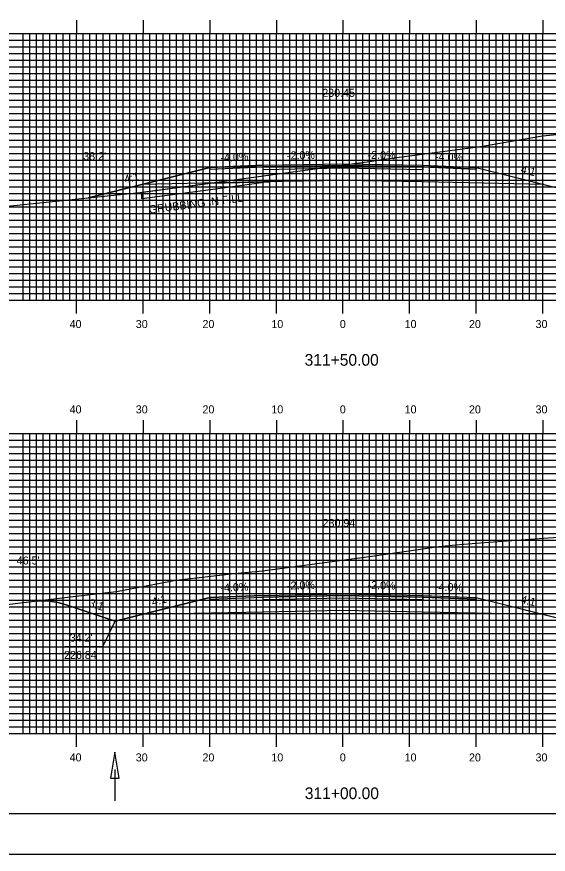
# Model space of a CAD drawing. Extents: x 1818457 to 1818800, y 442591 to 442811.
# Drawn here: x 1818573.7 to 1818653.4, y 442590.5 to 442716.2 of the extents above; entities that cross this region are included whole.
import ezdxf

# ---------------------------------------------------------------- set-up
doc = ezdxf.new("R2010")
doc.units = 0
for name, color, linetype in [('ANNOTATION', 7, 'Continuous'), ('BORDER', 7, 'Continuous'), ('D_Drainage_Ditch_Line', 7, 'Continuous'), ('D_Roadway_Centerline', 7, 'Continuous'), ('D_Roadway_Centerline_Text', 7, 'Continuous'), ('D_Roadway_Edge_Shoulder', 7, 'Continuous'), ('D_Roadway_Edge_TW', 7, 'Continuous'), ('D_Roadway_Pavement', 7, 'Continuous'), ('D_Roadway_SlopeLines', 7, 'Continuous'), ('D_Roadway_SubGrade', 7, 'Continuous'), ('D_Text_Standard', 7, 'Continuous'), ('GRUBBING IN FILL', 7, 'Continuous'), ('H_V ANNOTATION', 7, 'Continuous'), ('MAJOR', 7, 'Continuous'), ('MINOR', 7, 'Continuous'), ('PLOT BOUNDARY', 7, 'Continuous'), ('S_Roadway_Centerline', 7, 'Continuous')]:
    doc.layers.add(name, color=color, linetype=linetype)

msp = doc.modelspace()

# ---------------------------------------------------------------- linework, layer by layer
at = {"layer": 'ANNOTATION'}
msp.add_lwpolyline([(1818580.89, 442621.71), (1818586.58, 442621.71), (1818588.46, 442625.5)], dxfattribs=at)
at = {"layer": 'BORDER'}
msp.add_lwpolyline([(1818473.04, 442596.67), (1818793.04, 442596.67), (1818793.04, 442806.67), (1818473.04, 442806.67)], close=True, dxfattribs=at)
at = {"layer": 'D_Drainage_Ditch_Line'}
msp.add_line((1818588.38, 442603.26), (1818588.38, 442598.56), dxfattribs=at)
msp.add_lwpolyline([(1818587.72, 442601.95), (1818589.03, 442601.95), (1818588.38, 442605.88)], close=True, dxfattribs=at)
at = {"layer": 'D_Roadway_Centerline'}
for points in [[(1818584.45, 442689.01), (1818590.64, 442690.56), (1818592.46, 442691.02), (1818602.64, 442693.56), (1818610.64, 442693.88), (1818622.64, 442694.12), (1818634.64, 442693.88), (1818642.64, 442693.56), (1818652.81, 442691.02), (1818656.81, 442690.02), (1818690.05, 442701.1), (1818691.3, 442701.47), (1818692.55, 442701.76), (1818693.8, 442701.97), (1818695.05, 442702.1)], [(1818576.1, 442628.49), (1818577.35, 442628.57), (1818578.6, 442628.51), (1818579.85, 442628.3), (1818581.1, 442627.96), (1818588.46, 442625.5), (1818592.46, 442626.5), (1818602.64, 442629.05), (1818610.64, 442629.37), (1818622.64, 442629.61), (1818634.64, 442629.37), (1818642.64, 442629.05), (1818652.81, 442626.5), (1818656.81, 442625.5), (1818703.88, 442641.19), (1818705.13, 442641.57), (1818706.38, 442641.86), (1818707.63, 442642.06), (1818708.88, 442642.19)]]:
    msp.add_lwpolyline(points, dxfattribs=at)
at = {"layer": 'D_Roadway_Edge_Shoulder'}
for points in [[(1818610.64, 442693.88), (1818602.64, 442693.56), (1818602.64, 442693.31), (1818610.64, 442693.63)], [(1818634.64, 442693.88), (1818642.64, 442693.56), (1818642.64, 442693.31), (1818634.64, 442693.63)], [(1818610.64, 442629.37), (1818602.64, 442629.05), (1818602.64, 442628.8), (1818610.64, 442629.12)], [(1818634.64, 442629.37), (1818642.64, 442629.05), (1818642.64, 442628.8), (1818634.64, 442629.12)]]:
    msp.add_lwpolyline(points, close=True, dxfattribs=at)
at = {"layer": 'D_Roadway_Edge_TW'}
for points in [[(1818610.64, 442693.63), (1818610.64, 442693.88), (1818622.64, 442694.12), (1818634.64, 442693.88), (1818634.64, 442693.63), (1818622.64, 442693.87)], [(1818610.64, 442629.12), (1818610.64, 442629.37), (1818622.64, 442629.61), (1818634.64, 442629.37), (1818634.64, 442629.12), (1818622.64, 442629.36)]]:
    msp.add_lwpolyline(points, close=True, dxfattribs=at)
at = {"layer": 'D_Roadway_Pavement'}
for points in [[(1818610.64, 442693.21), (1818610.64, 442693.63), (1818622.64, 442693.87), (1818634.64, 442693.63), (1818634.64, 442693.21), (1818622.64, 442693.45)], [(1818610.64, 442628.7), (1818610.64, 442629.12), (1818622.64, 442629.36), (1818634.64, 442629.12), (1818634.64, 442628.7), (1818622.64, 442628.94)]]:
    msp.add_lwpolyline(points, close=True, dxfattribs=at)
at = {"layer": 'D_Roadway_SlopeLines'}
for points in [[(1818602.64, 442693.56), (1818592.46, 442691.02), (1818590.64, 442690.56), (1818584.45, 442689.01)], [(1818642.64, 442693.56), (1818656.81, 442690.02)], [(1818588.46, 442625.5), (1818581.1, 442627.96), (1818579.85, 442628.3), (1818578.6, 442628.51), (1818577.35, 442628.57), (1818576.1, 442628.49)], [(1818602.64, 442629.05), (1818588.46, 442625.5)], [(1818642.64, 442629.05), (1818656.81, 442625.5)]]:
    msp.add_lwpolyline(points, dxfattribs=at)
at = {"layer": 'D_Roadway_SubGrade'}
for points in [[(1818610.64, 442691.38), (1818592.46, 442691.02), (1818602.64, 442693.56), (1818602.64, 442693.31), (1818610.64, 442693.63), (1818622.64, 442693.87), (1818634.64, 442693.63), (1818642.64, 442693.31), (1818642.64, 442693.56), (1818652.81, 442691.02), (1818634.64, 442691.38), (1818622.64, 442691.62)], [(1818610.64, 442626.87), (1818592.46, 442626.5), (1818602.64, 442629.05), (1818602.64, 442628.8), (1818610.64, 442629.12), (1818622.64, 442629.36), (1818634.64, 442629.12), (1818642.64, 442628.8), (1818642.64, 442629.05), (1818652.81, 442626.5), (1818634.64, 442626.87), (1818622.64, 442627.11)]]:
    msp.add_lwpolyline(points, close=True, dxfattribs=at)
at = {"layer": 'GRUBBING IN FILL'}
msp.add_lwpolyline([(1818592.46, 442689.84), (1818602.73, 442691.22), (1818611.52, 442691.4), (1818602.73, 442690.21), (1818592.46, 442688.83)], close=True, dxfattribs=at)
msp.add_lwpolyline([(1818592.46, 442689.84), (1818602.73, 442691.22), (1818611.52, 442691.4), (1818602.73, 442690.21), (1818592.46, 442688.83)], close=True, dxfattribs=at)
at = {"layer": 'MAJOR'}
for p, q in [((1818582.64, 442715.67), (1818582.64, 442713.67)), ((1818592.64, 442715.67), (1818592.64, 442713.67)), ((1818602.64, 442715.67), (1818602.64, 442713.67)), ((1818612.64, 442715.67), (1818612.64, 442713.67)), ((1818622.64, 442715.67), (1818622.64, 442713.67)), ((1818632.64, 442715.67), (1818632.64, 442713.67)), ((1818642.64, 442715.67), (1818642.64, 442713.67)), ((1818652.64, 442715.67), (1818652.64, 442713.67)), ((1818482.64, 442713.67), (1818762.64, 442713.67)), ((1818482.64, 442713.67), (1818762.64, 442713.67)), ((1818582.64, 442673.67), (1818582.64, 442713.67)), ((1818592.64, 442673.67), (1818592.64, 442713.67)), ((1818602.64, 442673.67), (1818602.64, 442713.67)), ((1818612.64, 442673.67), (1818612.64, 442713.67)), ((1818622.64, 442673.67), (1818622.64, 442713.67)), ((1818632.64, 442673.67), (1818632.64, 442713.67)), ((1818642.64, 442673.67), (1818642.64, 442713.67)), ((1818652.64, 442673.67), (1818652.64, 442713.67)), ((1818482.64, 442708.67), (1818762.64, 442708.67)), ((1818482.64, 442703.67), (1818762.64, 442703.67)), ((1818482.64, 442698.67), (1818762.64, 442698.67)), ((1818482.64, 442693.67), (1818762.64, 442693.67)), ((1818482.64, 442688.67), (1818762.64, 442688.67)), ((1818482.64, 442683.67), (1818762.64, 442683.67)), ((1818482.64, 442678.67), (1818762.64, 442678.67)), ((1818482.64, 442673.67), (1818762.64, 442673.67)), ((1818482.64, 442673.67), (1818762.64, 442673.67)), ((1818582.64, 442671.66), (1818582.64, 442673.67)), ((1818592.64, 442671.66), (1818592.64, 442673.67)), ((1818602.64, 442671.66), (1818602.64, 442673.67)), ((1818612.64, 442671.66), (1818612.64, 442673.67)), ((1818622.64, 442671.66), (1818622.64, 442673.67)), ((1818632.64, 442671.66), (1818632.64, 442673.67)), ((1818642.64, 442671.66), (1818642.64, 442673.67)), ((1818652.64, 442671.66), (1818652.64, 442673.67)), ((1818582.64, 442655.67), (1818582.64, 442653.67)), ((1818592.64, 442655.67), (1818592.64, 442653.67)), ((1818602.64, 442655.67), (1818602.64, 442653.67)), ((1818612.64, 442655.67), (1818612.64, 442653.67)), ((1818622.64, 442655.67), (1818622.64, 442653.67)), ((1818632.64, 442655.67), (1818632.64, 442653.67)), ((1818642.64, 442655.67), (1818642.64, 442653.67)), ((1818652.64, 442655.67), (1818652.64, 442653.67)), ((1818482.64, 442653.67), (1818762.64, 442653.67)), ((1818482.64, 442653.67), (1818762.64, 442653.67)), ((1818582.64, 442608.67), (1818582.64, 442653.67)), ((1818592.64, 442608.67), (1818592.64, 442653.67)), ((1818602.64, 442608.67), (1818602.64, 442653.67)), ((1818612.64, 442608.67), (1818612.64, 442653.67)), ((1818622.64, 442608.67), (1818622.64, 442653.67)), ((1818632.64, 442608.67), (1818632.64, 442653.67)), ((1818642.64, 442608.67), (1818642.64, 442653.67)), ((1818652.64, 442608.67), (1818652.64, 442653.67)), ((1818482.64, 442648.67), (1818762.64, 442648.67)), ((1818482.64, 442643.67), (1818762.64, 442643.67)), ((1818482.64, 442638.67), (1818762.64, 442638.67)), ((1818482.64, 442633.67), (1818762.64, 442633.67)), ((1818482.64, 442628.67), (1818762.64, 442628.67)), ((1818482.64, 442623.67), (1818762.64, 442623.67)), ((1818482.64, 442618.67), (1818762.64, 442618.67)), ((1818482.64, 442613.67), (1818762.64, 442613.67)), ((1818482.64, 442608.67), (1818762.64, 442608.67)), ((1818482.64, 442608.67), (1818762.64, 442608.67)), ((1818582.64, 442606.66), (1818582.64, 442608.67)), ((1818592.64, 442606.66), (1818592.64, 442608.67)), ((1818602.64, 442606.66), (1818602.64, 442608.67)), ((1818612.64, 442606.66), (1818612.64, 442608.67)), ((1818622.64, 442606.66), (1818622.64, 442608.67)), ((1818632.64, 442606.66), (1818632.64, 442608.67)), ((1818642.64, 442606.66), (1818642.64, 442608.67)), ((1818652.64, 442606.66), (1818652.64, 442608.67))]:
    msp.add_line(p, q, dxfattribs=at)
at = {"layer": 'MINOR'}
for p, q in [((1818574.64, 442673.67), (1818574.64, 442713.67)), ((1818575.64, 442673.67), (1818575.64, 442713.67)), ((1818576.64, 442673.67), (1818576.64, 442713.67)), ((1818577.64, 442673.67), (1818577.64, 442713.67)), ((1818578.64, 442673.67), (1818578.64, 442713.67)), ((1818579.64, 442673.67), (1818579.64, 442713.67)), ((1818580.64, 442673.67), (1818580.64, 442713.67)), ((1818581.64, 442673.67), (1818581.64, 442713.67)), ((1818583.64, 442673.67), (1818583.64, 442713.67)), ((1818584.64, 442673.67), (1818584.64, 442713.67)), ((1818585.64, 442673.67), (1818585.64, 442713.67)), ((1818586.64, 442673.67), (1818586.64, 442713.67)), ((1818587.64, 442673.67), (1818587.64, 442713.67)), ((1818588.64, 442673.67), (1818588.64, 442713.67)), ((1818589.64, 442673.67), (1818589.64, 442713.67)), ((1818590.64, 442673.67), (1818590.64, 442713.67)), ((1818591.64, 442673.67), (1818591.64, 442713.67)), ((1818593.64, 442673.67), (1818593.64, 442713.67)), ((1818594.64, 442673.67), (1818594.64, 442713.67)), ((1818595.64, 442673.67), (1818595.64, 442713.67)), ((1818596.64, 442673.67), (1818596.64, 442713.67)), ((1818597.64, 442673.67), (1818597.64, 442713.67)), ((1818598.64, 442673.67), (1818598.64, 442713.67)), ((1818599.64, 442673.67), (1818599.64, 442713.67)), ((1818600.64, 442673.67), (1818600.64, 442713.67)), ((1818601.64, 442673.67), (1818601.64, 442713.67)), ((1818603.64, 442673.67), (1818603.64, 442713.67)), ((1818604.64, 442673.67), (1818604.64, 442713.67)), ((1818605.64, 442673.67), (1818605.64, 442713.67)), ((1818606.64, 442673.67), (1818606.64, 442713.67)), ((1818607.64, 442673.67), (1818607.64, 442713.67)), ((1818608.64, 442673.67), (1818608.64, 442713.67)), ((1818609.64, 442673.67), (1818609.64, 442713.67)), ((1818610.64, 442673.67), (1818610.64, 442713.67)), ((1818611.64, 442673.67), (1818611.64, 442713.67)), ((1818613.64, 442673.67), (1818613.64, 442713.67)), ((1818614.64, 442673.67), (1818614.64, 442713.67)), ((1818615.64, 442673.67), (1818615.64, 442713.67)), ((1818616.64, 442673.67), (1818616.64, 442713.67)), ((1818617.64, 442673.67), (1818617.64, 442713.67)), ((1818618.64, 442673.67), (1818618.64, 442713.67)), ((1818619.64, 442673.67), (1818619.64, 442713.67)), ((1818620.64, 442673.67), (1818620.64, 442713.67)), ((1818621.64, 442673.67), (1818621.64, 442713.67)), ((1818623.64, 442673.67), (1818623.64, 442713.67)), ((1818624.64, 442673.67), (1818624.64, 442713.67)), ((1818625.64, 442673.67), (1818625.64, 442713.67)), ((1818626.64, 442673.67), (1818626.64, 442713.67)), ((1818627.64, 442673.67), (1818627.64, 442713.67)), ((1818628.64, 442673.67), (1818628.64, 442713.67)), ((1818629.64, 442673.67), (1818629.64, 442713.67)), ((1818630.64, 442673.67), (1818630.64, 442713.67)), ((1818631.64, 442673.67), (1818631.64, 442713.67)), ((1818633.64, 442673.67), (1818633.64, 442713.67)), ((1818634.64, 442673.67), (1818634.64, 442713.67)), ((1818635.64, 442673.67), (1818635.64, 442713.67)), ((1818636.64, 442673.67), (1818636.64, 442713.67)), ((1818637.64, 442673.67), (1818637.64, 442713.67)), ((1818638.64, 442673.67), (1818638.64, 442713.67)), ((1818639.64, 442673.67), (1818639.64, 442713.67)), ((1818640.64, 442673.67), (1818640.64, 442713.67)), ((1818641.64, 442673.67), (1818641.64, 442713.67)), ((1818643.64, 442673.67), (1818643.64, 442713.67)), ((1818644.64, 442673.67), (1818644.64, 442713.67)), ((1818645.64, 442673.67), (1818645.64, 442713.67)), ((1818646.64, 442673.67), (1818646.64, 442713.67)), ((1818647.64, 442673.67), (1818647.64, 442713.67)), ((1818648.64, 442673.67), (1818648.64, 442713.67)), ((1818649.64, 442673.67), (1818649.64, 442713.67)), ((1818650.64, 442673.67), (1818650.64, 442713.67)), ((1818651.64, 442673.67), (1818651.64, 442713.67)), ((1818482.64, 442712.67), (1818762.64, 442712.67)), ((1818482.64, 442711.67), (1818762.64, 442711.67)), ((1818482.64, 442710.67), (1818762.64, 442710.67)), ((1818482.64, 442709.67), (1818762.64, 442709.67)), ((1818482.64, 442707.67), (1818762.64, 442707.67)), ((1818482.64, 442706.67), (1818762.64, 442706.67)), ((1818482.64, 442705.67), (1818762.64, 442705.67)), ((1818482.64, 442704.67), (1818762.64, 442704.67)), ((1818482.64, 442702.67), (1818762.64, 442702.67)), ((1818482.64, 442701.67), (1818762.64, 442701.67)), ((1818482.64, 442700.67), (1818762.64, 442700.67)), ((1818482.64, 442699.67), (1818762.64, 442699.67)), ((1818482.64, 442697.67), (1818762.64, 442697.67)), ((1818482.64, 442696.67), (1818762.64, 442696.67)), ((1818482.64, 442695.67), (1818762.64, 442695.67)), ((1818482.64, 442694.67), (1818762.64, 442694.67)), ((1818482.64, 442692.67), (1818762.64, 442692.67)), ((1818482.64, 442691.67), (1818762.64, 442691.67)), ((1818482.64, 442690.67), (1818762.64, 442690.67)), ((1818482.64, 442689.67), (1818762.64, 442689.67)), ((1818482.64, 442687.67), (1818762.64, 442687.67)), ((1818482.64, 442686.67), (1818762.64, 442686.67)), ((1818482.64, 442685.67), (1818762.64, 442685.67)), ((1818482.64, 442684.67), (1818762.64, 442684.67)), ((1818482.64, 442682.67), (1818762.64, 442682.67)), ((1818482.64, 442681.67), (1818762.64, 442681.67)), ((1818482.64, 442680.67), (1818762.64, 442680.67)), ((1818482.64, 442679.67), (1818762.64, 442679.67)), ((1818482.64, 442677.67), (1818762.64, 442677.67)), ((1818482.64, 442676.67), (1818762.64, 442676.67)), ((1818482.64, 442675.67), (1818762.64, 442675.67)), ((1818482.64, 442674.67), (1818762.64, 442674.67)), ((1818574.64, 442608.67), (1818574.64, 442653.67)), ((1818575.64, 442608.67), (1818575.64, 442653.67)), ((1818576.64, 442608.67), (1818576.64, 442653.67)), ((1818577.64, 442608.67), (1818577.64, 442653.67)), ((1818578.64, 442608.67), (1818578.64, 442653.67)), ((1818579.64, 442608.67), (1818579.64, 442653.67)), ((1818580.64, 442608.67), (1818580.64, 442653.67)), ((1818581.64, 442608.67), (1818581.64, 442653.67)), ((1818583.64, 442608.67), (1818583.64, 442653.67)), ((1818584.64, 442608.67), (1818584.64, 442653.67)), ((1818585.64, 442608.67), (1818585.64, 442653.67)), ((1818586.64, 442608.67), (1818586.64, 442653.67)), ((1818587.64, 442608.67), (1818587.64, 442653.67)), ((1818588.64, 442608.67), (1818588.64, 442653.67)), ((1818589.64, 442608.67), (1818589.64, 442653.67)), ((1818590.64, 442608.67), (1818590.64, 442653.67)), ((1818591.64, 442608.67), (1818591.64, 442653.67)), ((1818593.64, 442608.67), (1818593.64, 442653.67)), ((1818594.64, 442608.67), (1818594.64, 442653.67)), ((1818595.64, 442608.67), (1818595.64, 442653.67)), ((1818596.64, 442608.67), (1818596.64, 442653.67)), ((1818597.64, 442608.67), (1818597.64, 442653.67)), ((1818598.64, 442608.67), (1818598.64, 442653.67)), ((1818599.64, 442608.67), (1818599.64, 442653.67)), ((1818600.64, 442608.67), (1818600.64, 442653.67)), ((1818601.64, 442608.67), (1818601.64, 442653.67)), ((1818603.64, 442608.67), (1818603.64, 442653.67)), ((1818604.64, 442608.67), (1818604.64, 442653.67)), ((1818605.64, 442608.67), (1818605.64, 442653.67)), ((1818606.64, 442608.67), (1818606.64, 442653.67)), ((1818607.64, 442608.67), (1818607.64, 442653.67)), ((1818608.64, 442608.67), (1818608.64, 442653.67)), ((1818609.64, 442608.67), (1818609.64, 442653.67)), ((1818610.64, 442608.67), (1818610.64, 442653.67)), ((1818611.64, 442608.67), (1818611.64, 442653.67)), ((1818613.64, 442608.67), (1818613.64, 442653.67)), ((1818614.64, 442608.67), (1818614.64, 442653.67)), ((1818615.64, 442608.67), (1818615.64, 442653.67)), ((1818616.64, 442608.67), (1818616.64, 442653.67)), ((1818617.64, 442608.67), (1818617.64, 442653.67)), ((1818618.64, 442608.67), (1818618.64, 442653.67)), ((1818619.64, 442608.67), (1818619.64, 442653.67)), ((1818620.64, 442608.67), (1818620.64, 442653.67)), ((1818621.64, 442608.67), (1818621.64, 442653.67)), ((1818623.64, 442608.67), (1818623.64, 442653.67)), ((1818624.64, 442608.67), (1818624.64, 442653.67)), ((1818625.64, 442608.67), (1818625.64, 442653.67)), ((1818626.64, 442608.67), (1818626.64, 442653.67)), ((1818627.64, 442608.67), (1818627.64, 442653.67)), ((1818628.64, 442608.67), (1818628.64, 442653.67)), ((1818629.64, 442608.67), (1818629.64, 442653.67)), ((1818630.64, 442608.67), (1818630.64, 442653.67)), ((1818631.64, 442608.67), (1818631.64, 442653.67)), ((1818633.64, 442608.67), (1818633.64, 442653.67)), ((1818634.64, 442608.67), (1818634.64, 442653.67)), ((1818635.64, 442608.67), (1818635.64, 442653.67)), ((1818636.64, 442608.67), (1818636.64, 442653.67)), ((1818637.64, 442608.67), (1818637.64, 442653.67)), ((1818638.64, 442608.67), (1818638.64, 442653.67)), ((1818639.64, 442608.67), (1818639.64, 442653.67)), ((1818640.64, 442608.67), (1818640.64, 442653.67)), ((1818641.64, 442608.67), (1818641.64, 442653.67)), ((1818643.64, 442608.67), (1818643.64, 442653.67)), ((1818644.64, 442608.67), (1818644.64, 442653.67)), ((1818645.64, 442608.67), (1818645.64, 442653.67)), ((1818646.64, 442608.67), (1818646.64, 442653.67)), ((1818647.64, 442608.67), (1818647.64, 442653.67)), ((1818648.64, 442608.67), (1818648.64, 442653.67)), ((1818649.64, 442608.67), (1818649.64, 442653.67)), ((1818650.64, 442608.67), (1818650.64, 442653.67)), ((1818651.64, 442608.67), (1818651.64, 442653.67)), ((1818482.64, 442652.67), (1818762.64, 442652.67)), ((1818482.64, 442651.67), (1818762.64, 442651.67)), ((1818482.64, 442650.67), (1818762.64, 442650.67)), ((1818482.64, 442649.67), (1818762.64, 442649.67)), ((1818482.64, 442647.67), (1818762.64, 442647.67)), ((1818482.64, 442646.67), (1818762.64, 442646.67)), ((1818482.64, 442645.67), (1818762.64, 442645.67)), ((1818482.64, 442644.67), (1818762.64, 442644.67)), ((1818482.64, 442642.67), (1818762.64, 442642.67)), ((1818482.64, 442641.67), (1818762.64, 442641.67)), ((1818482.64, 442640.67), (1818762.64, 442640.67)), ((1818482.64, 442639.67), (1818762.64, 442639.67)), ((1818482.64, 442637.67), (1818762.64, 442637.67)), ((1818482.64, 442636.67), (1818762.64, 442636.67)), ((1818482.64, 442635.67), (1818762.64, 442635.67)), ((1818482.64, 442634.67), (1818762.64, 442634.67)), ((1818482.64, 442632.67), (1818762.64, 442632.67)), ((1818482.64, 442631.67), (1818762.64, 442631.67)), ((1818482.64, 442630.67), (1818762.64, 442630.67)), ((1818482.64, 442629.67), (1818762.64, 442629.67)), ((1818482.64, 442627.67), (1818762.64, 442627.67)), ((1818482.64, 442626.67), (1818762.64, 442626.67)), ((1818482.64, 442625.67), (1818762.64, 442625.67)), ((1818482.64, 442624.67), (1818762.64, 442624.67)), ((1818482.64, 442622.67), (1818762.64, 442622.67)), ((1818482.64, 442621.67), (1818762.64, 442621.67)), ((1818482.64, 442620.67), (1818762.64, 442620.67)), ((1818482.64, 442619.67), (1818762.64, 442619.67)), ((1818482.64, 442617.67), (1818762.64, 442617.67)), ((1818482.64, 442616.67), (1818762.64, 442616.67)), ((1818482.64, 442615.67), (1818762.64, 442615.67)), ((1818482.64, 442614.67), (1818762.64, 442614.67)), ((1818482.64, 442612.67), (1818762.64, 442612.67)), ((1818482.64, 442611.67), (1818762.64, 442611.67)), ((1818482.64, 442610.67), (1818762.64, 442610.67)), ((1818482.64, 442609.67), (1818762.64, 442609.67))]:
    msp.add_line(p, q, dxfattribs=at)
at = {"layer": 'PLOT BOUNDARY'}
msp.add_lwpolyline([(1818456.85, 442590.55), (1818796.85, 442590.55), (1818796.85, 442810.55), (1818456.85, 442810.55)], close=True, dxfattribs=at)
at = {"layer": 'S_Roadway_Centerline'}
for points in [[(1818558.62, 442686.34), (1818592.64, 442689.86), (1818624.71, 442694.18), (1818626.66, 442694.46), (1818628.43, 442694.76), (1818643.28, 442696.68), (1818652.59, 442698.28), (1818659.99, 442699.02), (1818673.9, 442700.48), (1818677.73, 442700.87), (1818679.7, 442701.16), (1818687.16, 442701.55), (1818695.53, 442702.14), (1818698.53, 442702.3), (1818712.14, 442703.56), (1818720.25, 442703.99), (1818728.64, 442704.61), (1818742.98, 442705.29), (1818747.44, 442705.45), (1818752.79, 442705.66), (1818759.89, 442705.98), (1818762.64, 442706.21)], [(1818572.16, 442628.02), (1818582.15, 442629.22), (1818588.63, 442629.97), (1818597.53, 442631.66), (1818606.3, 442632.63), (1818610.55, 442633.07), (1818626.97, 442635.25), (1818637.03, 442636.68), (1818639.51, 442636.95), (1818644.55, 442637.34), (1818656.22, 442638.21), (1818663.19, 442639.18), (1818673.33, 442639.73), (1818677.55, 442639.86), (1818689.08, 442640.76), (1818690.2, 442640.85), (1818690.56, 442640.87), (1818704, 442641.84), (1818707.32, 442642.1), (1818713.43, 442642.45)]]:
    msp.add_lwpolyline(points, dxfattribs=at)

# ---------------------------------------------------------------- texts
at = {"layer": 'ANNOTATION'}
for s, rotation, p in [('-4.0%', 2.2906, (1818604.27, 442694.43)), ('-2.0%', 1.1458, (1818614.24, 442694.75)), ('-2.0%', 358.8542, (1818626.32, 442694.85)), ('-4.0%', 357.7094, (1818636.43, 442694.61)), ('4:1', 345.9638, (1818649.23, 442692.77)), ('4:1', 14.0362, (1818589.97, 442691.15)), ('-4.0%', 2.2906, (1818604.27, 442629.91)), ('-2.0%', 1.1458, (1818614.24, 442630.24)), ('-2.0%', 358.8542, (1818626.32, 442630.33)), ('-4.0%', 357.7094, (1818636.43, 442630.1)), ('3:1', 341.5652, (1818584.39, 442627.77)), ('4:1', 14.0362, (1818594.09, 442627.77)), ('4:1', 345.9638, (1818649.23, 442628.26))]:
    msp.add_text(s, height=1.2, rotation=rotation, dxfattribs=at).set_placement(p)
for s, p in [("34.2'", (1818581.62, 442622.44)), ('226.84', (1818580.77, 442619.84))]:
    msp.add_text(s, height=1.2, dxfattribs=at).set_placement(p)
at = {"layer": 'D_Roadway_Centerline'}
for s, p in [('C', (1818622.63, 442694.12)), ('L', (1818622.64, 442694.11)), ('C', (1818622.63, 442629.61)), ('L', (1818622.64, 442629.6))]:
    msp.add_text(s, height=0.0146, dxfattribs=at).set_placement(p)
at = {"layer": 'D_Roadway_Centerline_Text'}
for s, p in [('230.45', (1818619.53, 442704.15)), ('230.94', (1818619.57, 442639.64))]:
    msp.add_text(s, height=1.2, dxfattribs=at).set_placement(p)
at = {"layer": 'D_Text_Standard'}
for s, p in [("38.2'", (1818583.65, 442694.64)), ("46.5'", (1818573.67, 442634.01))]:
    msp.add_text(s, height=1.2, dxfattribs=at).set_placement(p)
at = {"layer": 'GRUBBING IN FILL'}
msp.add_text('GRUBBING IN FILL', height=1.2, rotation=7.3014, dxfattribs=at).set_placement((1818593.57, 442686.63))
at = {"layer": 'H_V ANNOTATION'}
for s, height, p in [('40', 1.2, (1818581.61, 442669.47)), ('30', 1.2, (1818591.54, 442669.47)), ('20', 1.2, (1818601.55, 442669.47)), ('10', 1.2, (1818611.89, 442669.47)), ('0', 1.2, (1818622.16, 442669.47)), ('10', 1.2, (1818631.89, 442669.47)), ('20', 1.2, (1818641.55, 442669.47)), ('30', 1.2, (1818651.54, 442669.47)), ('311+50.00', 1.75, (1818616.88, 442663.82)), ('40', 1.2, (1818581.61, 442656.67)), ('30', 1.2, (1818591.54, 442656.67)), ('20', 1.2, (1818601.55, 442656.67)), ('10', 1.2, (1818611.89, 442656.67)), ('0', 1.2, (1818622.16, 442656.67)), ('10', 1.2, (1818631.89, 442656.67)), ('20', 1.2, (1818641.55, 442656.67)), ('30', 1.2, (1818651.54, 442656.67)), ('40', 1.2, (1818581.61, 442604.47)), ('30', 1.2, (1818591.54, 442604.47)), ('20', 1.2, (1818601.55, 442604.47)), ('10', 1.2, (1818611.89, 442604.47)), ('0', 1.2, (1818622.16, 442604.47)), ('10', 1.2, (1818631.89, 442604.47)), ('20', 1.2, (1818641.55, 442604.47)), ('30', 1.2, (1818651.54, 442604.47)), ('311+00.00', 1.75, (1818616.91, 442598.82))]:
    msp.add_text(s, height=height, dxfattribs=at).set_placement(p)

doc.saveas('drawing.dxf')
